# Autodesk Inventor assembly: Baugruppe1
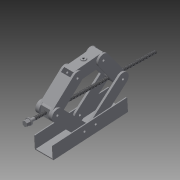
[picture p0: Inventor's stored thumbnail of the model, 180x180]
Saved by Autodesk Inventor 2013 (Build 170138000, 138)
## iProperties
Created: 2012-11
Part Number: Baugruppe1
Document SubType Name: Assembly
Designer: macuser
Author: macuser
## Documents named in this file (8)
- Y:\Inventor Wagenheber\Baugruppe1.iam
- Y:\Inventor Wagenheber\unterkasten.ipt
- Y:\Inventor Wagenheber\schenkl.ipt
- Y:\Inventor Wagenheber\hülse.ipt
- Y:\Inventor Wagenheber\krone.ipt
- Y:\Inventor Wagenheber\Teller.ipt
- Y:\Inventor Wagenheber\Welle.ipt
- Y:\Inventor Wagenheber\schenkl 2.ipt
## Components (12 placed, 7 different names)
1. unterkasten:1 — Passend:1, Fluchtend:1, Passend:2, Fluchtend:2, Fluchtend:3, Passend:3, Passend:4, Fluchtend:4
2. schenkl:1 — Passend:1, Fluchtend:1, Fluchtend:12, Passend:30
3. schenkl:2 — Passend:2, Fluchtend:2, Passend:25, Fluchtend:13
4. schenkl:3 — Fluchtend:3, Passend:3, Fluchtend:14, Passend:32, Passend:33
5. schenkl:4 — Passend:4, Fluchtend:4, Passend:27
6. hülse:1 — Passend:24, Passend:33
7. hülse:2 — Fluchtend:12, Winkel:1, Passend:23, Passend:31
8. krone:1 — Einfügen:1, Fluchtend:15, Passend:28, Passend:29
9. Teller:1 — Einfügen:1
10. Welle:1 — Winkel:1, Passend:23, Passend:24
11. schenkl 2:1 — Passend:25, Fluchtend:13, Fluchtend:15, Passend:29, Passend:30, Passend:31
12. schenkl 2:2 — Passend:27, Fluchtend:14, Passend:28, Passend:32
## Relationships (24: Mate 14, Flush 8, Insert 1, Angle 1)
- Passend:1 [Mate]: unterkasten:1 ↔ schenkl:1
- Fluchtend:1 [Flush]: unterkasten:1 ↔ schenkl:1
- Passend:2 [Mate]: unterkasten:1 ↔ schenkl:2
- Fluchtend:2 [Flush]: unterkasten:1 ↔ schenkl:2
- Fluchtend:3 [Flush]: unterkasten:1 ↔ schenkl:3
- Passend:3 [Mate]: unterkasten:1 ↔ schenkl:3
- Passend:4 [Mate]: unterkasten:1 ↔ schenkl:4
- Fluchtend:4 [Flush]: unterkasten:1 ↔ schenkl:4
- Fluchtend:12 [Flush]: schenkl:1 ↔ hülse:2
- Einfügen:1 [Insert]: krone:1 ↔ Teller:1
- Winkel:1 [Angle]: hülse:2 ↔ Welle:1
- Passend:23 [Mate]: hülse:2 ↔ Welle:1
- Passend:24 [Mate]: hülse:1 ↔ Welle:1
- Passend:25 [Mate]: schenkl:2 ↔ schenkl 2:1
- Passend:27 [Mate]: schenkl:4 ↔ schenkl 2:2
- Fluchtend:13 [Flush]: schenkl:2 ↔ schenkl 2:1
- Fluchtend:14 [Flush]: schenkl:3 ↔ schenkl 2:2
- Fluchtend:15 [Flush]: krone:1 ↔ schenkl 2:1
- Passend:28 [Mate]: krone:1 ↔ schenkl 2:2
- Passend:29 [Mate]: krone:1 ↔ schenkl 2:1
- Passend:30 [Mate]: schenkl:1 ↔ schenkl 2:1
- Passend:31 [Mate]: hülse:2 ↔ schenkl 2:1
- Passend:32 [Mate]: schenkl:3 ↔ schenkl 2:2
- Passend:33 [Mate]: schenkl:3 ↔ hülse:1
## Named parameters: weg = 175 deg
